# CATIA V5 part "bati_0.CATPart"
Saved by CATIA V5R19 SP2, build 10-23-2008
Part number: bati_0
Bounding box of the stored display mesh (mm): x -20 to 20, y -25 to 132.001, z -13.333 to 165
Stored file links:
  D:\Dropbox\IAO_2011\MMS_GR2\IAO_2011_1492_afeiguel\IAO_2011_1492_afeiguel\bati_0.CATPart
  D:\Dropbox\IAO_2011\MMS_GR2\IAO_2011_1492_afeiguel\IAO_2011_1492_afeiguel\bielle_2.CATPart
  D:\Dropbox\IAO_2011\MMS_GR2\IAO_2011_1492_afeiguel\IAO_2011_1492_afeiguel\bielle_1.CATPart
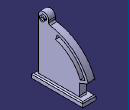
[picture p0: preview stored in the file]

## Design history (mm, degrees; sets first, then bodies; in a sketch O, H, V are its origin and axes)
Parameters
  AD = 150 mm
  rayonA_ext = 15 mm
  rayona_int = 5 mm
  `rayon_glissière` = 125 mm {= 5/6*AD}
  e_rainure = 15 mm
  `épaisseur` = 20 mm
External parameters (linked from other documents)
  External.r_tetebielle = 8 mm
  External.e_bielle = 5 mm
Body1 (main body)
  Sketch1 on yz-plane, origin (0, 0, 0), H (0, 1, 0), V (0, 0, 1)
    point P1 (0, 0)
    point P2 (0, 150)
    line L1 (0, 0) -> (0, 150)
    arc A1 centre (0, 0) radius 125 from (119.5992, 36.3462) to (30.9091, 121.1182) ccw
    distance P2 O = 150 {= AD}
    radius A1 = 125 {= `rayon_glissière`}
    coincidence: P1 O, P2 V
    vertical: L1 V
  Sketch2 on zx-plane, origin (0, 0, 0), H (-1, 0, 0), V (0, 0, 1)
    line L1 (-49.8432, 0) -> (44.8141, 0)
    point P1 (-49.8432, 0)
    line L2 (-49.8432, 150) -> (44.8141, 150)
    reference projected point E1 (0, 150) from Sketch1.P2
    distance L2 E1 = 0
    coincidence: P1 H
    horizontal: L1 H, L2 H
  Sketch3 on yz-plane, origin (0, 0, 0), H (0, 1, 0), V (0, 0, 1)
    line L1 (-15, 0) -> (-15, 150)
    point P1 (-15, 0)
    point P2 (-15, 150)
    arc A1 centre (0, 150) radius 15 from (15, 150) to (-15, 150) ccw
    point P3 (0, 150)
    point P4 (15, 150)
    reference projected point E1 (0, 150) from Sketch1.P2
    line L2 (-15, 0) -> (106.25, 0)
    line L3 (106.25, 0) -> (106.25, 35)
    circle A2 centre (0, 150) radius 4
    point P7 (3.8682, 151.0184)
    reference projected point E2 (0, 150) from Sketch1.P2
    line L4 (15, 150) -> (15, 139.697)
    arc A3 centre (0, 0) radius 140.5 from (132.79, 45.9029) to (15, 139.697) ccw
    line L5 (106.25, 35) -> (132.79, 45.9029)
    arc A4 centre (0, 0) radius 132.5 from (122.5609, 50.3495) to (40.2107, 126.2511) ccw
    line L6 (40.2107, 126.2511) -> (35.6585, 111.9586)
    line L7 (122.5609, 50.3495) -> (108.6861, 44.6495)
    arc A5 centre (0, 0) radius 117.5 from (108.6861, 44.6495) to (35.6585, 111.9586) ccw
    reference projected arc E3 centre (0, 0) radius 125 from (119.5992, 36.3462) to (30.9091, 121.1182) ccw from Sketch1.A1
    radius A1 = 15 {= rayonA_ext}
    distance E2 A2 = 4 {= External.r_tetebielle -4mm}
    length L6 = 15 {= e_rainure}
    distance A4 E3 = 7.5 {= e_rainure/2}
    distance A4 A3 = 8
    distance L7 L5 = 8
    length L3 = 35
    angle L7 L6 = 50
    distance P4 P2 = 30 {= rayonA_ext*2}
    length L2 = 121.25 {= `rayon_glissière` -e_rainure /4}
    coincidence: P1 H, P3 V, E1 P3, A2 P7, L6 O, L7 O
    vertical: L1 V, L3 V, L4 V
    tangency: A1 L1
    horizontal: L2 H
  Pad1: profile Sketch3, direction (1, 0, 0), length 10 {= `épaisseur` /2}, opposite side length 10 {= `épaisseur` /2}
  Sketch4 on face of Pad1 from Sketch3.L2, origin (0, 0, 0), H (1, 0, 0), V (0, -1, 0)
    line L1 (-20, 25) -> (20, 25)
    line L2 (20, 25) -> (20, -126.25)
    line L3 (20, -126.25) -> (-20, -126.25)
    line L4 (-20, -126.25) -> (-20, 25)
    reference projected line E1 (-10, 15) -> (10, 15) from edge [face of Pad1 from Sketch3.L2 | face of Pad1 from Sketch3.L1]
    reference projected line E2 (-10, -106.25) -> (10, -106.25) from edge [face of Pad1 from Sketch3.L3 | face of Pad1 from Sketch3.L2]
    reference projected line E3 (0, -119.5992) -> (0, -30.9091) from Sketch1.A1
    distance L2 L4 = 40 {= `épaisseur` *2}
    distance L1 E1 = 10
    distance E2 L3 = 20
    distance L2 E3 = 20 {= `épaisseur`}
    horizontal: L1 H, L3 H
    vertical: L2 V, L4 V
  Pad2: profile Sketch4, direction (0, 0, -1), length 13.3333 {= 2/3*`épaisseur`}
  Fillet1: radius 3, on edge [start face of Pad2 | face of Pad2 from Sketch4.L3]; edge [face of Pad1 from Sketch3.L3 | start face of Pad2]; edge [start face of Pad2 | face of Pad2 from Sketch4.L1]; edge [start face of Pad2 | face of Pad1 from Sketch3.L1]; edge [start face of Pad2 | face of Pad2 from Sketch4.L4]; edge [start face of Pad2 | face of Pad2 from Sketch4.L2]; edge [face of Pad1 from Sketch3.A3 | face of Pad1 from Sketch3.L5]
  Fillet2: radius 5 {= rayona_int}, on edge [face of Pad1 from Sketch3.L4 | face of Pad1 from Sketch3.A3]
  Sketch5 on end face of Pad1, origin (10, 0, 0), H (0, 1, 0), V (0, 0, 1)
    circle A1 centre (0, 150) radius 8
    point P1 (0, 150)
    circle A2 centre (0, 150) radius 4
    reference projected point E1 (0, 150) from Sketch1.P2
    radius A2 = 4 {= Sketch5.radius(A1) -4mm}
    radius A1 = 8 {= External.r_tetebielle}
    distance P1 E1 = 0
    coincidence: P1 V
  Pad3: profile Sketch5, direction (1, 0, 0), length 5 {= External.e_bielle}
